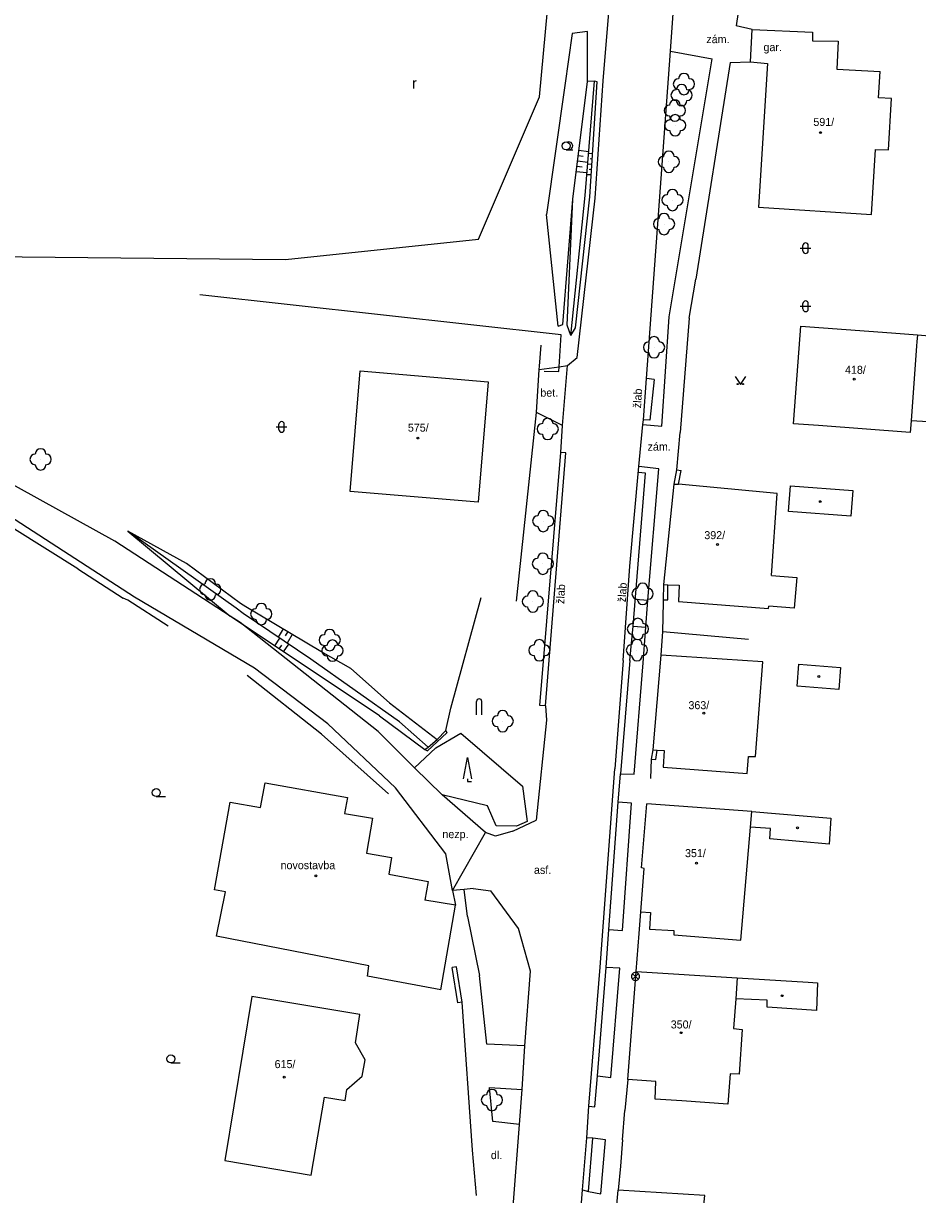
# Model space of a CAD drawing. Extents: x -737488 to -734267, y -1145775 to -1142573.
# Drawn here: x -736723.4 to -736639.5, y -1144564.3 to -1144454.6 of the extents above; entities that cross this region are included whole.
import ezdxf

# ---------------------------------------------------------------- set-up
doc = ezdxf.new("R2010")
doc.units = 0
for name, color, linetype in [('Vrstva 1', 7, 'Continuous'), ('Vrstva 10', 7, 'Continuous'), ('Vrstva 11', 7, 'Continuous'), ('Vrstva 12', 7, 'Continuous'), ('Vrstva 14', 7, 'Continuous'), ('Vrstva 3', 7, 'Continuous'), ('Vrstva 4', 7, 'Continuous'), ('Vrstva 5', 7, 'Continuous'), ('Vrstva 6', 7, 'Continuous'), ('Vrstva 8', 7, 'Continuous'), ('Vrstva 9', 7, 'Continuous')]:
    doc.layers.add(name, color=color, linetype=linetype)

# ---------------------------------------------------------------- blocks, each defined once
blk = doc.blocks.new('1.030')
at = {"layer": 'Vrstva 1'}
for points in [[(-0.53, 0.53), (-0.57, 0.49), (-0.6, 0.45), (-0.63, 0.41), (-0.66, 0.36), (-0.68, 0.32), (-0.7, 0.27), (-0.72, 0.22), (-0.73, 0.17), (-0.74, 0.12), (-0.75, 0.07), (-0.75, 0.01), (-0.75, -0.04), (-0.74, -0.09), (-0.74, -0.14), (-0.72, -0.19), (-0.71, -0.24), (-0.69, -0.29), (-0.67, -0.34), (-0.64, -0.39), (-0.61, -0.43), (-0.58, -0.47), (-0.53, -0.53), (0, 0)], [(0.53, -0.53), (0.57, -0.49), (0.6, -0.45), (0.63, -0.41), (0.66, -0.37), (0.68, -0.32), (0.7, -0.27), (0.72, -0.22), (0.73, -0.17), (0.74, -0.12), (0.75, -0.07), (0.75, -0.01), (0.75, 0.04), (0.75, 0.09), (0.74, 0.14), (0.73, 0.19), (0.71, 0.24), (0.69, 0.29), (0.67, 0.34), (0.64, 0.39), (0.62, 0.43), (0.58, 0.47), (0.53, 0.53), (0, 0)]]:
    blk.add_lwpolyline(points, close=True, dxfattribs=at)
for start, end in [(44.9922, 135.0078), (224.9922, 315.0078)]:
    blk.add_arc((0, 0), 0.75, start, end, dxfattribs=at)
blk = doc.blocks.new('3.130')
at = {"layer": 'Vrstva 1'}
blk.add_circle((0, 0), 0.001, dxfattribs=at)
for centre, start, end in [((-1, 0), 90, 270), ((0, 1), 0, 180), ((1, 0), 270, 90), ((0, -1), 180, 360)]:
    blk.add_arc(centre, 1, start, end, dxfattribs=at)
blk = doc.blocks.new('3.019')
at = {"layer": 'Vrstva 1'}
blk.add_text('r', height=2, dxfattribs=at).set_placement((-0.496, -0.964))
blk = doc.blocks.new('3.040')
at = {"layer": 'Vrstva 1'}
blk.add_line((0, -0.75), (1.75, -0.75), dxfattribs=at)
blk.add_circle((0, 0), 0.75, dxfattribs=at)
blk = doc.blocks.new('3.090')
at = {"layer": 'Vrstva 1'}
for points in [[(-0.75, 0), (0, 4), (0.75, 0)], [(0, 0), (0, -0.5), (0.75, -0.5)]]:
    blk.add_lwpolyline(points, dxfattribs=at)
blk = doc.blocks.new('3.110')
at = {"layer": 'Vrstva 1'}
blk.add_line((0, -0.75), (1.25, -0.75), dxfattribs=at)
blk.add_circle((0, 0), 0.75, dxfattribs=at)
blk.add_arc((0.5, 0), 0.75, 249.4944, 109.0474, dxfattribs=at)
blk = doc.blocks.new('3.140')
at = {"layer": 'Vrstva 1'}
blk.add_lwpolyline([(-1, 1.5), (0, 0), (1, 1.5)], dxfattribs=at)
for centre in [(-0.5, 0.1), (0.5, 0.1)]:
    blk.add_circle(centre, 0.1, dxfattribs=at)
blk = doc.blocks.new('3.160')
at = {"layer": 'Vrstva 1'}
for p, q in [((-1, 0), (1, 0)), ((-0.5, -0.5), (-0.5, 0.5)), ((0.5, -0.5), (0.5, 0.5))]:
    blk.add_line(p, q, dxfattribs=at)
for centre, start, end in [((0, 0.5), 0, 180), ((0, -0.5), 180, 360)]:
    blk.add_arc(centre, 0.5, start, end, dxfattribs=at)
blk = doc.blocks.new('4.020')
at = {"layer": 'Vrstva 1'}
blk.add_circle((0, 0), 0.175, dxfattribs=at)
blk = doc.blocks.new('4.140')
at = {"layer": 'Vrstva 1'}
for p, q in [((-0.5, 0), (-0.5, 2.5)), ((0.5, 0), (0.5, 2.5))]:
    blk.add_line(p, q, dxfattribs=at)
blk.add_arc((0, 2.5), 0.5, 0, 180, dxfattribs=at)

msp = doc.modelspace()

# ---------------------------------------------------------------- linework, layer by layer
at = {"layer": 'Vrstva 10'}
for points in [[(-736669.01, -1144459.94), (-736666.86, -1144433.96)], [(-736662.69, -1144457.14), (-736662.45, -1144453.61)], [(-736664.94, -1144487.85), (-736662.69, -1144457.14)], [(-736663.53, -1144492.32), (-736662.82, -1144482.05), (-736658.8, -1144457.87)], [(-736662.69, -1144457.14), (-736658.8, -1144457.87)], [(-736671.45, -1144485.88), (-736669.77, -1144470.92), (-736669.01, -1144459.94)], [(-736672.38, -1144486.63), (-736671.45, -1144485.88)], [(-736675.02, -1144487.01), (-736673.16, -1144486.74), (-736672.38, -1144486.63)], [(-736672.83, -1144492.24), (-736672.38, -1144486.63)], [(-736665.29, -1144492.16), (-736665.25, -1144491.71), (-736664.94, -1144487.85)], [(-736664.23, -1144487.93), (-736664.94, -1144487.85)], [(-736664.23, -1144487.93), (-736664.64, -1144491.73)], [(-736672.83, -1144492.24), (-736675.27, -1144491.03)], [(-736664.64, -1144491.73), (-736665.25, -1144491.71)], [(-736673, -1144494.78), (-736672.83, -1144492.24)], [(-736665.68, -1144496.09), (-736665.29, -1144492.16)], [(-736665.29, -1144492.16), (-736663.53, -1144492.32)], [(-736714.83, -1144503.1), (-736729.15, -1144495.17)], [(-736674.95, -1144518.5), (-736673, -1144494.78)], [(-736674.43, -1144518.54), (-736672.51, -1144494.81)], [(-736672.51, -1144494.81), (-736673, -1144494.78)], [(-736666.53, -1144505.43), (-736665.68, -1144496.09)], [(-736663.79, -1144496.32), (-736665.68, -1144496.09)], [(-736664.83, -1144508.61), (-736663.79, -1144496.32)], [(-736712.98, -1144508.33), (-736730.33, -1144497.13)], [(-736666.21, -1144511.07), (-736665.05, -1144496.71)], [(-736665.05, -1144496.71), (-736665.73, -1144496.65)], [(-736704.02, -1144510.12), (-736714.83, -1144503.1)], [(-736667.13, -1144514.29), (-736666.53, -1144505.43)], [(-736701.72, -1144515), (-736712.98, -1144508.33)], [(-736666, -1144508.52), (-736664.83, -1144508.61)], [(-736665.26, -1144514.48), (-736664.83, -1144508.61)], [(-736703.07, -1144510.72), (-736704.02, -1144510.12)], [(-736690.13, -1144520.94), (-736703.07, -1144510.72)], [(-736666.51, -1144514.28), (-736666.21, -1144511.07)], [(-736666.21, -1144511.07), (-736665.02, -1144511.16)], [(-736694.84, -1144520.21), (-736701.72, -1144515)], [(-736667.13, -1144514.29), (-736667.91, -1144524.44)], [(-736666.51, -1144514.28), (-736667.39, -1144524.89)], [(-736666.12, -1144524.94), (-736665.26, -1144514.48)], [(-736674.43, -1144518.54), (-736674.95, -1144518.5)], [(-736674.43, -1144518.54), (-736674.35, -1144519.87)], [(-736688.51, -1144526.2), (-736694.84, -1144520.21)], [(-736674.35, -1144519.87), (-736675.29, -1144529.24)], [(-736686.72, -1144524.34), (-736690.13, -1144520.94)], [(-736684.11, -1144526.86), (-736686.72, -1144524.34)], [(-736669.3, -1144543.04), (-736667.91, -1144524.44)], [(-736667.6, -1144527.57), (-736667.39, -1144524.89)], [(-736667.39, -1144524.89), (-736666.12, -1144524.94)], [(-736683.77, -1144532.4), (-736688.51, -1144526.2)], [(-736680.07, -1144530.4), (-736684.11, -1144526.86)], [(-736668.49, -1144539.5), (-736667.6, -1144527.57)], [(-736666.36, -1144527.66), (-736667.6, -1144527.57)], [(-736667.21, -1144539.59), (-736666.36, -1144527.66)], [(-736677.5, -1144530.28), (-736675.29, -1144529.24)], [(-736683.14, -1144535.85), (-736680.07, -1144530.4)], [(-736679.11, -1144530.74), (-736680.07, -1144530.4)], [(-736677.5, -1144530.28), (-736679.11, -1144530.74)], [(-736683.14, -1144535.85), (-736683.77, -1144532.4)], [(-736682.05, -1144535.75), (-736683.14, -1144535.85)], [(-736683.14, -1144535.85), (-736682.86, -1144537.21)], [(-736681.21, -1144535.65), (-736682.05, -1144535.75)], [(-736681.74, -1144538.27), (-736682.05, -1144535.75)], [(-736681.21, -1144535.65), (-736679.56, -1144535.86)], [(-736676.96, -1144539.39), (-736679.56, -1144535.86)], [(-736681.74, -1144538.27), (-736680.63, -1144543.8)], [(-736675.83, -1144543.39), (-736676.96, -1144539.39)], [(-736668.74, -1144543.07), (-736668.49, -1144539.5)], [(-736668.49, -1144539.5), (-736667.21, -1144539.59)], [(-736676.36, -1144550.4), (-736675.83, -1144543.39)], [(-736670.37, -1144556.07), (-736669.3, -1144543.04)], [(-736669.55, -1144553.21), (-736668.74, -1144543.07)], [(-736667.47, -1144543.13), (-736668.74, -1144543.07)], [(-736668.29, -1144553.37), (-736667.47, -1144543.13)], [(-736679.92, -1144550.23), (-736680.63, -1144543.8)], [(-736676.36, -1144550.4), (-736679.92, -1144550.23)], [(-736676.61, -1144554.5), (-736676.36, -1144550.4)], [(-736669.79, -1144556.11), (-736669.55, -1144553.21)], [(-736669.55, -1144553.21), (-736668.29, -1144553.37)], [(-736679.36, -1144557.49), (-736679.67, -1144554.32)], [(-736679.67, -1144554.32), (-736676.61, -1144554.5)], [(-736676.86, -1144557.77), (-736676.61, -1144554.5)], [(-736670.56, -1144559.03), (-736670.37, -1144556.07)], [(-736670.37, -1144556.07), (-736669.79, -1144556.11)], [(-736676.86, -1144557.77), (-736679.36, -1144557.49)], [(-736677.46, -1144565.47), (-736676.86, -1144557.77)], [(-736670.96, -1144563.91), (-736670.56, -1144559.03)], [(-736670, -1144559.07), (-736670.56, -1144559.03)], [(-736670.4, -1144564.06), (-736670, -1144559.07)], [(-736668.81, -1144559.2), (-736670, -1144559.07)], [(-736669.25, -1144564.26), (-736668.81, -1144559.2)], [(-736671.46, -1144570.33), (-736670.96, -1144563.91)], [(-736670.96, -1144563.91), (-736670.4, -1144564.06)], [(-736670.4, -1144564.06), (-736669.25, -1144564.26)]]:
    msp.add_lwpolyline(points, dxfattribs=at)
at = {"layer": 'Vrstva 11'}
for points in [[(-736674.99, -1144461.43), (-736672.55, -1144434.98)], [(-736671.93, -1144455.51), (-736672.6, -1144460.38)], [(-736670.5, -1144455.31), (-736671.93, -1144455.51)], [(-736670.49, -1144460), (-736670.5, -1144455.31)], [(-736671.88, -1144471.03), (-736670.49, -1144460)], [(-736672.6, -1144460.38), (-736674.35, -1144472.45)], [(-736680.72, -1144474.77), (-736674.99, -1144461.43)], [(-736672.81, -1144482.77), (-736671.88, -1144471.03)], [(-736673.24, -1144482.92), (-736674.35, -1144472.45)], [(-736698.82, -1144476.67), (-736680.72, -1144474.77)], [(-736751.36, -1144476.15), (-736698.82, -1144476.67)], [(-736673.24, -1144482.92), (-736672.81, -1144482.77)], [(-736684.73, -1144522.47), (-736682.36, -1144521.09)], [(-736682.36, -1144521.09), (-736676.6, -1144526.05)], [(-736686.72, -1144524.34), (-736684.73, -1144522.47)], [(-736676.6, -1144526.05), (-736676.15, -1144529.36)], [(-736679.87, -1144527.9), (-736684.11, -1144526.86)], [(-736679.06, -1144529.79), (-736679.87, -1144527.9)], [(-736676.15, -1144529.36), (-736677.15, -1144529.82)], [(-736677.15, -1144529.82), (-736679.06, -1144529.79)]]:
    msp.add_lwpolyline(points, dxfattribs=at)
at = {"layer": 'Vrstva 12'}
for points in [[(-736670.72, -1144470.67), (-736669.84, -1144459.97)], [(-736669.84, -1144459.97), (-736670.49, -1144460)], [(-736670.28, -1144470.8), (-736669.58, -1144460.03)], [(-736669.58, -1144460.03), (-736669.84, -1144459.97)], [(-736671.3, -1144466.43), (-736670.38, -1144466.55)], [(-736670.02, -1144466.77), (-736670.4, -1144466.74)], [(-736671.49, -1144467.92), (-736671, -1144467.98)], [(-736671.43, -1144467.42), (-736670.46, -1144467.55)], [(-736671.36, -1144466.93), (-736670.89, -1144466.99)], [(-736670.08, -1144467.77), (-736670.48, -1144467.74)], [(-736670.05, -1144467.27), (-736670.24, -1144467.26)], [(-736671.55, -1144468.42), (-736670.54, -1144468.54)], [(-736670.15, -1144468.76), (-736670.56, -1144468.74)], [(-736670.12, -1144468.27), (-736670.32, -1144468.25)], [(-736672.4, -1144482.84), (-736671.88, -1144471.03)], [(-736672.05, -1144483.8), (-736670.72, -1144470.67)], [(-736671.6, -1144483.08), (-736670.28, -1144470.8)], [(-736672.05, -1144483.8), (-736672.4, -1144482.84)], [(-736672.05, -1144483.8), (-736671.6, -1144483.08)], [(-736713.61, -1144502.14), (-736704.02, -1144510.12)], [(-736703.46, -1144509.38), (-736713.61, -1144502.14)], [(-736708.09, -1144505.19), (-736713.61, -1144502.14)], [(-736703.04, -1144508.94), (-736708.09, -1144505.19)], [(-736683.31, -1144518.74), (-736680.47, -1144508.37)], [(-736702.78, -1144509.86), (-736703.46, -1144509.38)], [(-736702.53, -1144509.23), (-736703.04, -1144508.94)], [(-736695.49, -1144513.43), (-736702.53, -1144509.23)], [(-736690, -1144519.45), (-736704.02, -1144510.12)], [(-736688.13, -1144520.02), (-736696.44, -1144514.15), (-736702.78, -1144509.86)], [(-736699.03, -1144511.32), (-736699.49, -1144512.08)], [(-736698.6, -1144511.57), (-736698.84, -1144511.97)], [(-736698.18, -1144511.83), (-736698.66, -1144512.64)], [(-736699.82, -1144512.91), (-736699.34, -1144512.19)], [(-736699.4, -1144513.19), (-736699.16, -1144512.83)], [(-736698.99, -1144513.47), (-736698.51, -1144512.75)], [(-736692.68, -1144515.04), (-736695.49, -1144513.43)], [(-736689.07, -1144518.23), (-736692.68, -1144515.04)], [(-736689.07, -1144518.23), (-736684.6, -1144521.69)], [(-736690, -1144519.45), (-736685.74, -1144522.63)], [(-736683.77, -1144520.85), (-736683.31, -1144518.74)], [(-736688.13, -1144520.02), (-736685.44, -1144522.4)]]:
    msp.add_lwpolyline(points, dxfattribs=at)
at = {"layer": 'Vrstva 4'}
for points in [[(-736655.21, -1144458.16), (-736655.03, -1144455.13)], [(-736662.35, -1144497.73), (-736662.1, -1144496.4)], [(-736662.1, -1144496.4), (-736661.71, -1144496.47)], [(-736661.95, -1144497.76), (-736661.71, -1144496.47)], [(-736663.34, -1144507.14), (-736662.35, -1144497.73)], [(-736662.35, -1144497.73), (-736661.95, -1144497.76)], [(-736663.36, -1144508.6), (-736663.34, -1144507.14)], [(-736663.34, -1144507.14), (-736662.94, -1144507.17)], [(-736662.96, -1144508.6), (-736662.94, -1144507.17)], [(-736663.36, -1144508.6), (-736662.96, -1144508.6)], [(-736664.34, -1144522.64), (-736663.58, -1144513.78)], [(-736664.47, -1144523.51), (-736664.34, -1144522.64)], [(-736664.34, -1144522.64), (-736663.94, -1144522.67)], [(-736664.07, -1144523.57), (-736663.94, -1144522.67)], [(-736664.47, -1144523.51), (-736664.07, -1144523.57)], [(-736665.41, -1144533.71), (-736664.93, -1144527.71)], [(-736665.49, -1144537.84), (-736665.17, -1144533.76)], [(-736665.17, -1144533.76), (-736665.41, -1144533.71)], [(-736682.86, -1144537.21), (-736685.76, -1144536.75)], [(-736684.26, -1144545.15), (-736682.86, -1144537.21)], [(-736682.79, -1144542.99), (-736683.18, -1144543.05)], [(-736682.64, -1144546.36), (-736683.18, -1144543.05)], [(-736682.25, -1144546.3), (-736682.79, -1144542.99)], [(-736666.71, -1144553.56), (-736665.91, -1144543.44)], [(-736684.26, -1144545.15), (-736691.12, -1144543.86)], [(-736682.25, -1144546.3), (-736682.64, -1144546.36)], [(-736668.23, -1144570.81), (-736667.6, -1144563.94)]]:
    msp.add_lwpolyline(points, dxfattribs=at)
at = {"layer": 'Vrstva 5'}
for points in [[(-736655.03, -1144455.13), (-736649.39, -1144455.37), (-736649.39, -1144456.17), (-736646.97, -1144456.2), (-736647.09, -1144458.85), (-736643.04, -1144459.07)], [(-736655.21, -1144458.16), (-736653.6, -1144458.3), (-736654.46, -1144471.78), (-736643.86, -1144472.45), (-736643.48, -1144466.38), (-736642.25, -1144466.41), (-736641.97, -1144461.58), (-736643.2, -1144461.52), (-736643.04, -1144459.07)], [(-736650.54, -1144483.77), (-736650.48, -1144482.92)], [(-736650.48, -1144482.92), (-736641.96, -1144483.55)], [(-736651.16, -1144492.09), (-736650.54, -1144483.77)], [(-736641.96, -1144483.55), (-736639.54, -1144483.73)], [(-736639.54, -1144483.73), (-736628.12, -1144484.68), (-736628.39, -1144485.85), (-736627.22, -1144485.9), (-736627.31, -1144488.2), (-736629.07, -1144488.16), (-736629.3, -1144492.45), (-736630.51, -1144492.38), (-736640.14, -1144491.82)], [(-736639.59, -1144484.41), (-736639.62, -1144484.77)], [(-736639.54, -1144483.73), (-736639.59, -1144484.41)], [(-736639.62, -1144484.77), (-736640.14, -1144491.82)], [(-736692.76, -1144498.42), (-736691.81, -1144487.13)], [(-736691.81, -1144487.13), (-736679.8, -1144488.14)], [(-736679.8, -1144488.14), (-736680.75, -1144499.43)], [(-736648.81, -1144492.26), (-736651.16, -1144492.09)], [(-736640.14, -1144491.82), (-736640.22, -1144492.9)], [(-736640.22, -1144492.9), (-736648.81, -1144492.26)], [(-736680.75, -1144499.43), (-736692.76, -1144498.42)], [(-736653.24, -1144506.3), (-736652.71, -1144498.63), (-736661.95, -1144497.76)], [(-736651.63, -1144500.31), (-736651.44, -1144497.89)], [(-736651.44, -1144497.89), (-736645.61, -1144498.34)], [(-736645.61, -1144498.34), (-736645.8, -1144500.76)], [(-736645.8, -1144500.76), (-736651.63, -1144500.31)], [(-736653.24, -1144506.3), (-736650.86, -1144506.5), (-736651.11, -1144509.38), (-736653.49, -1144509.18)], [(-736662.94, -1144507.17), (-736661.9, -1144507.21), (-736661.94, -1144508.74), (-736653.52, -1144509.41), (-736653.49, -1144509.18)], [(-736663.94, -1144522.67), (-736663.3, -1144522.71), (-736663.4, -1144524.29), (-736655.52, -1144524.87), (-736655.39, -1144523.26), (-736654.72, -1144523.26), (-736654.04, -1144514.4), (-736663.58, -1144513.78)], [(-736650.82, -1144516.69), (-736650.65, -1144514.61)], [(-736650.65, -1144514.61), (-736646.75, -1144514.92)], [(-736646.75, -1144514.92), (-736646.91, -1144517)], [(-736646.91, -1144517), (-736650.82, -1144516.69)], [(-736691.12, -1144543.86), (-736691.01, -1144542.91), (-736705.3, -1144540.11), (-736704.46, -1144535.96), (-736705.48, -1144535.76), (-736704, -1144527.57), (-736701.16, -1144528.07), (-736700.74, -1144525.74), (-736693, -1144527.11), (-736693.27, -1144528.61), (-736690.67, -1144529.06), (-736691.21, -1144532.34), (-736688.86, -1144532.75), (-736689.11, -1144534.31), (-736685.45, -1144534.98), (-736685.76, -1144536.75)], [(-736665.49, -1144537.84), (-736664.58, -1144537.89), (-736664.66, -1144539.47), (-736662.4, -1144539.59), (-736662.4, -1144539.99), (-736656.1, -1144540.5), (-736655.2, -1144529.9), (-736655.08, -1144528.43), (-736664.93, -1144527.71)], [(-736655.08, -1144528.43), (-736647.67, -1144529.06), (-736647.83, -1144531.48), (-736653.37, -1144531), (-736653.33, -1144530.01), (-736655.2, -1144529.9)], [(-736665.91, -1144543.44), (-736656.45, -1144544.03), (-736656.59, -1144546), (-736656.8, -1144548.78), (-736655.97, -1144548.86), (-736656.27, -1144553.06), (-736657.1, -1144553.03), (-736657.31, -1144555.86), (-736661.65, -1144555.56), (-736664.13, -1144555.39), (-736664.09, -1144553.75), (-736666.71, -1144553.56)], [(-736656.45, -1144544.03), (-736649.8, -1144544.44), (-736648.9, -1144544.5), (-736649.01, -1144547.09), (-736653.65, -1144546.79), (-736653.65, -1144546.13), (-736656.59, -1144546)], [(-736701.96, -1144545.78), (-736704.51, -1144561.15), (-736696.42, -1144562.52), (-736695.15, -1144555.21), (-736693.23, -1144555.51), (-736693.06, -1144554.5), (-736691.62, -1144553.25), (-736691.33, -1144551.71), (-736692.26, -1144550.12), (-736691.86, -1144547.47), (-736701.96, -1144545.78)], [(-736668.23, -1144570.81), (-736660.17, -1144571.39), (-736659.82, -1144567.83), (-736659.49, -1144564.43), (-736667.6, -1144563.94)]]:
    msp.add_lwpolyline(points, dxfattribs=at)
at = {"layer": 'Vrstva 9'}
for points in [[(-736653.81, -1144436.25), (-736656.55, -1144454.78)], [(-736655.03, -1144455.13), (-736656.55, -1144454.78)], [(-736657.12, -1144458.22), (-736660.34, -1144478.52)], [(-736657.12, -1144458.22), (-736655.21, -1144458.16)], [(-736660.96, -1144482.17), (-736660.34, -1144478.52)], [(-736672.95, -1144483.73), (-736706.85, -1144479.98)], [(-736660.96, -1144482.17), (-736661.79, -1144492.89)], [(-736673.19, -1144487.19), (-736673.16, -1144486.74), (-736672.95, -1144483.73)], [(-736675, -1144486.69), (-736674.83, -1144484.7)], [(-736675.27, -1144491.03), (-736675.02, -1144487.01)], [(-736675.02, -1144487.01), (-736675, -1144486.69)], [(-736674.54, -1144487.16), (-736673.19, -1144487.19)], [(-736677.16, -1144508.7), (-736675.27, -1144491.03)], [(-736662.1, -1144496.4), (-736661.79, -1144492.89)], [(-736718.31, -1144505.68), (-736730.47, -1144498.08)], [(-736718.31, -1144505.68), (-736714.03, -1144508.44)], [(-736713.6, -1144508.62), (-736714.03, -1144508.44)], [(-736709.81, -1144511.07), (-736713.6, -1144508.62)], [(-736663.43, -1144511.56), (-736663.37, -1144508.84)], [(-736663.37, -1144508.84), (-736663.36, -1144508.6)], [(-736663.58, -1144513.78), (-736663.43, -1144511.56)], [(-736663.43, -1144511.56), (-736655.38, -1144512.26)], [(-736695.45, -1144521.18), (-736702.4, -1144515.69)], [(-736689.16, -1144526.77), (-736695.45, -1144521.18)], [(-736685.49, -1144522.73), (-736683.68, -1144521.06)], [(-736685.44, -1144522.4), (-736684.6, -1144521.69)], [(-736684.6, -1144521.69), (-736683.77, -1144520.85)], [(-736683.77, -1144520.85), (-736683.68, -1144521.06)], [(-736685.74, -1144522.63), (-736685.44, -1144522.4)], [(-736685.74, -1144522.63), (-736685.49, -1144522.73)], [(-736664.56, -1144525.34), (-736664.47, -1144523.51)], [(-736665.65, -1144539.88), (-736665.49, -1144537.84)], [(-736665.91, -1144543.44), (-736665.65, -1144539.88)], [(-736681.27, -1144560.18), (-736682.25, -1144546.3)], [(-736666.71, -1144553.56), (-736666.98, -1144556.46)], [(-736667.2, -1144559.21), (-736666.98, -1144556.46)], [(-736667.2, -1144559.21), (-736667.39, -1144561.68), (-736667.6, -1144563.94)], [(-736680.9, -1144564.43), (-736681.27, -1144560.18)]]:
    msp.add_lwpolyline(points, dxfattribs=at)

# ---------------------------------------------------------------- block references
at = {"layer": 'Vrstva 1', "xscale": 0.5, "yscale": 0.5}
msp.add_blockref('1.030', (-736665.99, -1144543.9), dxfattribs=at)
at = {"layer": 'Vrstva 11', "xscale": 0.5, "yscale": 0.5}
for p in [(-736661.44, -1144460.23), (-736661.66, -1144461.28), (-736662.29, -1144462.71), (-736662.27, -1144464.1), (-736662.86, -1144467.52), (-736662.52, -1144471.11), (-736663.31, -1144473.36), (-736664.25, -1144484.91), (-736674.22, -1144492.57), (-736721.79, -1144495.42), (-736674.64, -1144501.2), (-736674.67, -1144505.2), (-736705.87, -1144507.61), (-736665.32, -1144508.03), (-736675.61, -1144508.74), (-736701.09, -1144509.92), (-736665.76, -1144511.32), (-736694.67, -1144512.36), (-736694.41, -1144513.35), (-736675, -1144513.32), (-736665.85, -1144513.3), (-736678.44, -1144519.96), (-736679.45, -1144555.48)]:
    msp.add_blockref('3.130', p, dxfattribs=at)
at = {"layer": 'Vrstva 3', "xscale": 0.5, "yscale": 0.5}
for name, p in [('3.019', (-736686.7, -1144460.17)), ('3.110', (-736672.5, -1144466.03)), ('3.160', (-736650.03, -1144475.62)), ('3.160', (-736650.03, -1144481.07)), ('3.140', (-736656.15, -1144488.41)), ('3.160', (-736699.18, -1144492.38)), ('3.090', (-736681.76, -1144525.37)), ('3.040', (-736710.94, -1144526.66)), ('3.040', (-736709.57, -1144551.62))]:
    msp.add_blockref(name, p, dxfattribs=at)
at = {"layer": 'Vrstva 8', "xscale": 0.5, "yscale": 0.5}
for p in [(-736648.63, -1144464.79), (-736645.46, -1144487.91), (-736686.41, -1144493.42), (-736648.65, -1144499.38), (-736658.3, -1144503.4), (-736648.78, -1144515.77), (-736659.58, -1144519.22), (-736650.79, -1144529.97), (-736660.26, -1144533.27), (-736695.96, -1144534.47), (-736652.23, -1144545.7), (-736661.71, -1144549.17), (-736698.93, -1144553.34)]:
    msp.add_blockref('4.020', p, dxfattribs=at)
at = {"layer": 'Vrstva 9', "xscale": 0.5, "yscale": 0.5}
msp.add_blockref('4.140', (-736680.65, -1144519.37), dxfattribs=at)

# ---------------------------------------------------------------- texts
at = {"layer": 'Vrstva 14'}
for s, p in [('zám.', (-736659.34, -1144456.4)), ('gar.', (-736653.98, -1144457.15)), ('bet.', (-736674.91, -1144489.54)), ('zám.', (-736664.85, -1144494.6)), ('nezp.', (-736684.1, -1144530.93)), ('novostavba', (-736699.28, -1144533.84)), ('asf.', (-736675.51, -1144534.28)), ('dl.', (-736679.55, -1144561.02))]:
    msp.add_text(s, height=0.75, dxfattribs=at).set_placement(p)
for p in [(-736665.47, -1144490.64), (-736672.68, -1144508.98), (-736666.9, -1144508.83)]:
    msp.add_text('žlab', height=0.75, rotation=86.864, dxfattribs=at).set_placement(p)
at = {"layer": 'Vrstva 6'}
for s, p in [('591/', (-736649.3, -1144464.16)), ('418/', (-736646.33, -1144487.4)), ('575/', (-736687.34, -1144492.82)), ('392/', (-736659.53, -1144502.9)), ('363/', (-736661.02, -1144518.84)), ('351/', (-736661.34, -1144532.71)), ('350/', (-736662.68, -1144548.77)), ('615/', (-736699.84, -1144552.49))]:
    msp.add_text(s, height=0.75, dxfattribs=at).set_placement(p)

doc.saveas('drawing.dxf')
